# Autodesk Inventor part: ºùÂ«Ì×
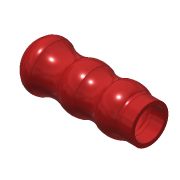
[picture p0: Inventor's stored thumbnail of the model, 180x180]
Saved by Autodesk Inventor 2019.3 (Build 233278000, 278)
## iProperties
Created: 2017-10
Part Number: ºùÂ«Ì×
Material: Ogólny
Document SubType Name: Modeling
Designer: CADENGINEERING4
Density: 1 g/cm^3
Appearance: Jasnoczerwona
Author: CADENGINEERING4
Revision Number: ÈÎºÎ
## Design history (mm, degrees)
feature "Ðý×ª2"
node "Bryła1"
